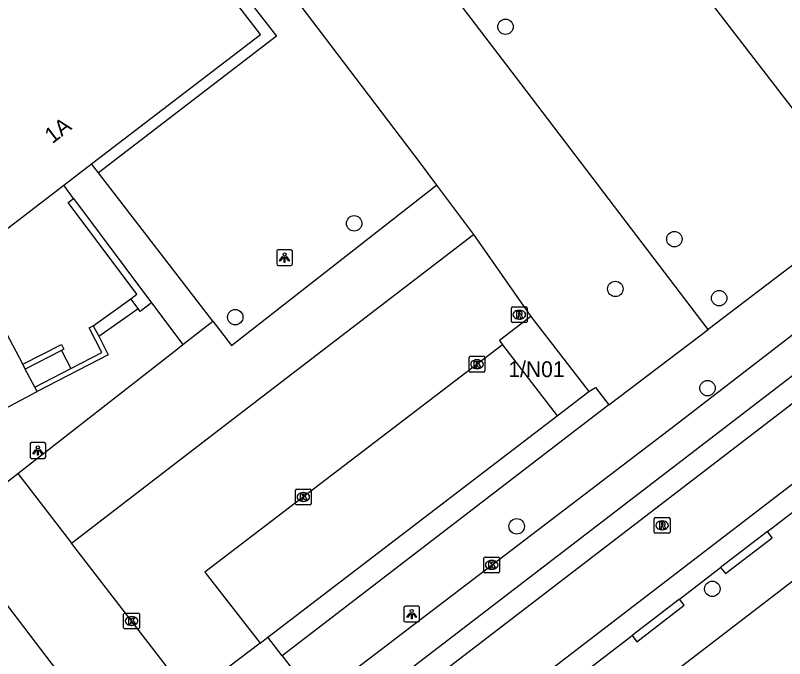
# Model space of a CAD drawing. Extents: x 159353 to 160616, y 385893 to 387321.
# Drawn here: x 159907.94 to 159956.75, y 386515.87 to 386556.66 of the extents above; entities that cross this region are included whole.
import ezdxf

# ---------------------------------------------------------------- set-up
doc = ezdxf.new("R2010")
doc.units = 0
for name, color, linetype in [('IMGEO_Boom', 7, 'Continuous'), ('IMGEO_Groenvoorziening', 7, 'Continuous'), ('IMGEO_Haag', 7, 'Continuous'), ('IMGEO_Kolk', 7, 'Continuous'), ('IMGEO_Lichtpunt', 7, 'Continuous'), ('IMGEO_Muur', 7, 'Continuous'), ('IMGEO_Pand', 7, 'Continuous'), ('IMGEO_Pand_nummerreeks', 7, 'Continuous'), ('IMGEO_Parkeervlak_open', 7, 'Continuous'), ('IMGEO_Rijbaan_lokaal_gesloten', 7, 'Continuous'), ('IMGEO_Rijbaan_lokaal_open', 7, 'Continuous'), ('IMGEO_Rioolput', 7, 'Continuous'), ('IMGEO_Voetpad_open', 7, 'Continuous')]:
    doc.layers.add(name, color=color, linetype=linetype)

msp = doc.modelspace()

# ---------------------------------------------------------------- linework, layer by layer
at = {"layer": 'IMGEO_Boom'}
for centre in [(159939.044, 386555.938), (159929.438, 386543.471), (159949.759, 386542.469), (159946.013, 386539.313), (159952.603, 386538.727), (159921.896, 386537.523), (159951.858, 386533.017), (159939.754, 386524.256), (159952.169, 386520.29)]:
    msp.add_circle(centre, 0.489, dxfattribs=at)
at = {"layer": 'IMGEO_Groenvoorziening'}
for points in [[(159951.895, 386536.745), (159940.008, 386552.331), (159922.277, 386575.578), (159898.089, 386607.292)], [(159918.33, 386563.284), (159920.36, 386564.743), (159933.568, 386547.368), (159934.672, 386545.892)], [(159918.33, 386563.284), (159924.505, 386555.352), (159913.211, 386546.671)]]:
    msp.add_lwpolyline(points, dxfattribs=at)
at = {"layer": 'IMGEO_Haag'}
msp.add_lwpolyline([(159944.324, 386532.797), (159944.745, 386533.066), (159945.59, 386531.953)], dxfattribs=at)
at = {"layer": 'IMGEO_Kolk'}
for p, q in [((159936.738, 386534.112), (159936.738, 386534.964)), ((159936.813, 386535.038), (159937.665, 386535.038)), ((159937.226, 386534.818), (159937.251, 386534.818)), ((159937.739, 386534.964), (159937.739, 386534.112)), ((159937.249, 386534.258), (159937.224, 386534.258)), ((159937.665, 386534.038), (159936.813, 386534.038)), ((159925.714, 386525.691), (159925.714, 386526.543)), ((159925.789, 386526.617), (159926.641, 386526.617)), ((159926.202, 386526.397), (159926.227, 386526.397)), ((159926.715, 386526.543), (159926.715, 386525.691)), ((159926.225, 386525.837), (159926.2, 386525.837)), ((159926.641, 386525.617), (159925.789, 386525.617)), ((159937.669, 386521.384), (159937.669, 386522.236)), ((159937.744, 386522.31), (159938.596, 386522.31)), ((159938.157, 386522.09), (159938.182, 386522.09)), ((159938.67, 386522.236), (159938.67, 386521.384)), ((159938.18, 386521.53), (159938.155, 386521.53)), ((159938.596, 386521.31), (159937.744, 386521.31)), ((159914.814, 386517.826), (159914.814, 386518.678)), ((159914.889, 386518.752), (159915.741, 386518.752)), ((159915.302, 386518.532), (159915.327, 386518.532)), ((159915.815, 386518.678), (159915.815, 386517.826)), ((159915.741, 386517.752), (159914.889, 386517.752)), ((159915.325, 386517.972), (159915.3, 386517.972))]:
    msp.add_line(p, q, dxfattribs=at)
for points in [[(159936.738, 386534.112), (159936.738, 386534.964)], [(159936.813, 386535.038), (159937.665, 386535.038)], [(159937.059, 386534.738), (159937.182, 386534.738), (159937.182, 386534.587), (159937.312, 386534.738), (159937.476, 386534.738), (159937.33, 386534.587), (159937.483, 386534.338), (159937.331, 386534.338), (159937.246, 386534.502), (159937.182, 386534.435), (159937.182, 386534.338), (159937.059, 386534.338), (159937.059, 386534.738)], [(159937.739, 386534.964), (159937.739, 386534.112)], [(159937.665, 386534.038), (159936.813, 386534.038)], [(159925.714, 386525.691), (159925.714, 386526.543)], [(159925.789, 386526.617), (159926.641, 386526.617)], [(159926.715, 386526.543), (159926.715, 386525.691)], [(159926.035, 386526.317), (159926.158, 386526.317), (159926.158, 386526.166), (159926.288, 386526.317), (159926.452, 386526.317), (159926.306, 386526.166), (159926.459, 386525.917), (159926.307, 386525.917), (159926.222, 386526.081), (159926.158, 386526.014), (159926.158, 386525.917), (159926.035, 386525.917), (159926.035, 386526.317)], [(159926.641, 386525.617), (159925.789, 386525.617)], [(159937.669, 386521.384), (159937.669, 386522.236)], [(159937.744, 386522.31), (159938.596, 386522.31)], [(159937.99, 386522.01), (159938.113, 386522.01), (159938.113, 386521.859), (159938.243, 386522.01), (159938.407, 386522.01), (159938.261, 386521.859), (159938.414, 386521.61), (159938.262, 386521.61), (159938.177, 386521.774), (159938.113, 386521.707), (159938.113, 386521.61), (159937.99, 386521.61), (159937.99, 386522.01)], [(159938.67, 386522.236), (159938.67, 386521.384)], [(159938.596, 386521.31), (159937.744, 386521.31)], [(159914.814, 386517.826), (159914.814, 386518.678)], [(159914.889, 386518.752), (159915.741, 386518.752)], [(159915.815, 386518.678), (159915.815, 386517.826)], [(159915.135, 386518.452), (159915.258, 386518.452), (159915.258, 386518.301), (159915.388, 386518.452), (159915.552, 386518.452), (159915.406, 386518.301), (159915.559, 386518.052), (159915.407, 386518.052), (159915.322, 386518.216), (159915.258, 386518.149), (159915.258, 386518.052), (159915.135, 386518.052), (159915.135, 386518.452)], [(159915.741, 386517.752), (159914.889, 386517.752)]]:
    msp.add_lwpolyline(points, dxfattribs=at)
for centre, start, end in [((159936.815, 386534.962), 91.552, 178.448), ((159936.815, 386534.962), 91.552, 178.448), ((159937.663, 386534.962), 1.552, 88.448), ((159937.663, 386534.962), 1.552, 88.448), ((159936.815, 386534.114), 181.552, 268.448), ((159936.815, 386534.114), 181.552, 268.448), ((159937.663, 386534.114), 271.552, 358.448), ((159937.663, 386534.114), 271.552, 358.448), ((159925.791, 386526.541), 91.552, 178.448), ((159925.791, 386526.541), 91.552, 178.448), ((159926.639, 386526.541), 1.552, 88.448), ((159926.639, 386526.541), 1.552, 88.448), ((159925.791, 386525.693), 181.552, 268.448), ((159925.791, 386525.693), 181.552, 268.448), ((159926.639, 386525.693), 271.552, 358.448), ((159926.639, 386525.693), 271.552, 358.448), ((159937.746, 386522.234), 91.552, 178.448), ((159937.746, 386522.234), 91.552, 178.448), ((159938.594, 386522.234), 1.552, 88.448), ((159938.594, 386522.234), 1.552, 88.448), ((159937.746, 386521.386), 181.552, 268.448), ((159937.746, 386521.386), 181.552, 268.448), ((159938.594, 386521.386), 271.552, 358.448), ((159938.594, 386521.386), 271.552, 358.448), ((159914.891, 386518.676), 91.552, 178.448), ((159914.891, 386518.676), 91.552, 178.448), ((159915.739, 386518.676), 1.552, 88.448), ((159915.739, 386518.676), 1.552, 88.448), ((159914.891, 386517.828), 181.552, 268.448), ((159914.891, 386517.828), 181.552, 268.448), ((159915.739, 386517.828), 271.552, 358.448), ((159915.739, 386517.828), 271.552, 358.448)]:
    msp.add_arc(centre, 0.0765, start, end, dxfattribs=at)
for centre, major_axis, ratio, start_param, end_param in [((159937.225, 386534.538), (-0.387, 0.002), 0.722429, 4.712389, 7.853982), ((159937.25, 386534.538), (-0.39, 0.002), 0.717154, 1.570796, 4.712389), ((159926.201, 386526.117), (-0.387, 0.002), 0.722429, 4.712389, 7.853982), ((159926.226, 386526.117), (-0.39, 0.002), 0.717154, 1.570796, 4.712389), ((159938.156, 386521.81), (-0.387, 0.002), 0.722429, 4.712389, 7.853982), ((159938.181, 386521.81), (-0.39, 0.002), 0.717154, 1.570796, 4.712389), ((159915.301, 386518.252), (-0.387, 0.002), 0.722429, 4.712389, 7.853982), ((159915.326, 386518.252), (-0.39, 0.002), 0.717154, 1.570796, 4.712389)]:
    msp.add_ellipse(centre, major_axis=major_axis, ratio=ratio, start_param=start_param, end_param=end_param, dxfattribs=at)
at = {"layer": 'IMGEO_Lichtpunt'}
for p, q in [((159924.526, 386541.701), (159924.526, 386540.894)), ((159924.526, 386541.701), (159924.526, 386540.894)), ((159925.428, 386541.796), (159924.62, 386541.796)), ((159925.428, 386541.796), (159924.62, 386541.796)), ((159925.522, 386540.894), (159925.522, 386541.701)), ((159925.522, 386540.894), (159925.522, 386541.701)), ((159924.62, 386540.8), (159925.428, 386540.8)), ((159924.62, 386540.8), (159925.428, 386540.8)), ((159908.872, 386529.468), (159908.872, 386528.661)), ((159908.872, 386529.468), (159908.872, 386528.661)), ((159909.774, 386529.563), (159908.966, 386529.563)), ((159909.774, 386529.563), (159908.966, 386529.563)), ((159909.868, 386528.661), (159909.868, 386529.468)), ((159909.868, 386528.661), (159909.868, 386529.468)), ((159908.966, 386528.567), (159909.774, 386528.567)), ((159908.966, 386528.567), (159909.774, 386528.567)), ((159932.594, 386519.092), (159932.594, 386518.285)), ((159932.594, 386519.092), (159932.594, 386518.285)), ((159933.496, 386519.187), (159932.688, 386519.187)), ((159933.496, 386519.187), (159932.688, 386519.187)), ((159933.59, 386518.285), (159933.59, 386519.092)), ((159933.59, 386518.285), (159933.59, 386519.092)), ((159932.688, 386518.191), (159933.496, 386518.191)), ((159932.688, 386518.191), (159933.496, 386518.191))]:
    msp.add_line(p, q, dxfattribs=at)
for points in [[(159924.9, 386541.365), (159924.939, 386541.337), (159924.751, 386541.075), (159924.713, 386541.102), (159924.9, 386541.365)], [(159925.002, 386541.317), (159925.049, 386541.317), (159925.049, 386540.995), (159925.002, 386540.995), (159925.002, 386541.317)], [(159925.112, 386541.337), (159925.15, 386541.364), (159925.337, 386541.102), (159925.298, 386541.074), (159925.112, 386541.337)], [(159909.246, 386529.132), (159909.285, 386529.104), (159909.097, 386528.842), (159909.059, 386528.869), (159909.246, 386529.132)], [(159909.348, 386529.084), (159909.395, 386529.084), (159909.395, 386528.762), (159909.348, 386528.762), (159909.348, 386529.084)], [(159909.458, 386529.104), (159909.496, 386529.131), (159909.683, 386528.869), (159909.644, 386528.841), (159909.458, 386529.104)], [(159932.968, 386518.756), (159933.007, 386518.728), (159932.819, 386518.466), (159932.781, 386518.493), (159932.968, 386518.756)], [(159933.07, 386518.708), (159933.117, 386518.708), (159933.117, 386518.386), (159933.07, 386518.386), (159933.07, 386518.708)], [(159933.18, 386518.728), (159933.218, 386518.755), (159933.405, 386518.493), (159933.366, 386518.465), (159933.18, 386518.728)]]:
    msp.add_lwpolyline(points, dxfattribs=at)
for centre in [(159925.025, 386541.499), (159909.371, 386529.266), (159933.093, 386518.89)]:
    msp.add_circle(centre, 0.0994, dxfattribs=at)
for centre, start, end in [((159924.62, 386541.701), 90, 180), ((159924.62, 386541.701), 90, 180), ((159925.428, 386541.701), 0, 90), ((159925.428, 386541.701), 0, 90), ((159924.62, 386540.894), 180, 270), ((159924.62, 386540.894), 180, 270), ((159925.428, 386540.894), 270, 0), ((159925.428, 386540.894), 270, 360), ((159908.966, 386529.468), 90, 180), ((159908.966, 386529.468), 90, 180), ((159909.774, 386529.468), 0, 90), ((159909.774, 386529.468), 0, 90), ((159908.966, 386528.661), 180, 270), ((159908.966, 386528.661), 180, 270), ((159909.774, 386528.661), 270, 0), ((159909.774, 386528.661), 270, 360), ((159932.688, 386519.092), 90, 180), ((159932.688, 386519.092), 90, 180), ((159933.496, 386519.092), 0, 90), ((159933.496, 386519.092), 0, 90), ((159932.688, 386518.285), 180, 270), ((159932.688, 386518.285), 180, 270), ((159933.496, 386518.285), 270, 0), ((159933.496, 386518.285), 270, 360)]:
    msp.add_arc(centre, 0.0946, start, end, dxfattribs=at)
at = {"layer": 'IMGEO_Muur'}
for points in [[(159915.277, 386538.684), (159915.64, 386538.98), (159911.292, 386544.804), (159911.633, 386545.058)], [(159911.633, 386545.058), (159916.586, 386538.424)], [(159915.736, 386538.069), (159915.277, 386538.684)], [(159916.586, 386538.424), (159915.87, 386537.889), (159915.736, 386538.069)], [(159911.459, 386534.256), (159913.433, 386535.272), (159912.622, 386536.846), (159912.886, 386536.982)], [(159912.886, 386536.982), (159913.229, 386536.316)], [(159913.229, 386536.316), (159913.837, 386535.135), (159909.321, 386532.811)], [(159908.409, 386534.534), (159910.864, 386535.798), (159911.024, 386535.487), (159910.866, 386535.406)], [(159910.866, 386535.406), (159908.573, 386534.224)], [(159909.178, 386533.081), (159911.459, 386534.256)]]:
    msp.add_lwpolyline(points, dxfattribs=at)
at = {"layer": 'IMGEO_Pand'}
for points in [[(159955.838, 386571.648), (159967.738, 386556.2), (159958.533, 386549.121), (159946.634, 386564.57)], [(159912.775, 386547.236), (159923.497, 386555.45), (159920.456, 386559.419), (159917.807, 386562.877)], [(159911.014, 386545.887), (159912.775, 386547.236)], [(159908.409, 386534.534), (159904.884, 386541.191), (159911.014, 386545.887)], [(159940.649, 386537.568), (159938.657, 386536.034), (159938.858, 386535.773)], [(159940.649, 386537.568), (159944.324, 386532.797)], [(159938.858, 386535.773), (159942.332, 386531.263)], [(159897.179, 386534.822), (159901.779, 386528.816), (159909.321, 386532.811)], [(159908.573, 386534.224), (159908.409, 386534.534)], [(159909.178, 386533.081), (159908.573, 386534.224)], [(159909.321, 386532.811), (159909.178, 386533.081)], [(159942.332, 386531.263), (159944.324, 386532.797)]]:
    msp.add_lwpolyline(points, dxfattribs=at)
at = {"layer": 'IMGEO_Parkeervlak_open'}
for points in [[(159920.47, 386537.273), (159921.661, 386535.731), (159934.672, 386545.892)], [(159934.672, 386545.892), (159937.004, 386542.774)], [(159923.967, 386517.223), (159942.332, 386531.263)], [(159908.093, 386527.599), (159911.495, 386523.195)], [(159914.482, 386510.005), (159906.02, 386521.077), (159905.493, 386521.701)]]:
    msp.add_lwpolyline(points, dxfattribs=at)
at = {"layer": 'IMGEO_Rijbaan_lokaal_gesloten'}
for points in [[(159876.924, 386472.328), (159899.739, 386489.718), (159978.286, 386549.954)], [(159859.708, 386457.258), (159979.14, 386548.844)], [(159981.625, 386545.617), (159862.162, 386454.007)], [(159955.666, 386523.932), (159962.814, 386529.415)], [(159955.666, 386523.932), (159952.696, 386521.654)], [(159950.078, 386519.645), (159952.696, 386521.654)], [(159950.078, 386519.645), (159947.079, 386517.33)], [(159938.561, 386510.815), (159944.357, 386515.23), (159947.079, 386517.33)]]:
    msp.add_lwpolyline(points, dxfattribs=at)
at = {"layer": 'IMGEO_Rijbaan_lokaal_open'}
for points in [[(159911.495, 386523.195), (159921.481, 386530.86), (159937.004, 386542.774)], [(159937.004, 386542.774), (159940.649, 386537.568)], [(159938.858, 386535.773), (159919.966, 386521.341), (159923.468, 386516.842)], [(159919.018, 386513.456), (159911.495, 386523.195)], [(159923.468, 386516.842), (159919.018, 386513.456)]]:
    msp.add_lwpolyline(points, dxfattribs=at)
at = {"layer": 'IMGEO_Rioolput'}
for p, q in [((159939.414, 386537.249), (159939.414, 386538.101)), ((159939.489, 386538.175), (159940.341, 386538.175)), ((159940.415, 386538.101), (159940.415, 386537.249)), ((159939.902, 386537.955), (159939.927, 386537.955)), ((159940.341, 386537.175), (159939.489, 386537.175)), ((159939.925, 386537.395), (159939.9, 386537.395)), ((159948.481, 386523.89), (159948.481, 386524.742)), ((159948.556, 386524.816), (159949.408, 386524.816)), ((159948.969, 386524.596), (159948.994, 386524.596)), ((159949.482, 386524.742), (159949.482, 386523.89)), ((159948.992, 386524.036), (159948.967, 386524.036)), ((159949.408, 386523.816), (159948.556, 386523.816))]:
    msp.add_line(p, q, dxfattribs=at)
for points in [[(159939.414, 386537.249), (159939.414, 386538.101)], [(159939.489, 386538.175), (159940.341, 386538.175)], [(159940.415, 386538.101), (159940.415, 386537.249)], [(159940.003, 386537.873), (159939.751, 386537.875), (159939.751, 386537.475)], [(159939.751, 386537.475), (159939.875, 386537.475), (159939.875, 386537.637), (159939.886, 386537.637)], [(159939.929, 386537.794), (159939.875, 386537.794), (159939.875, 386537.713)], [(159939.875, 386537.713), (159939.927, 386537.713)], [(159939.933, 386537.608), (159940.004, 386537.475), (159940.144, 386537.475), (159940.079, 386537.601)], [(159940.341, 386537.175), (159939.489, 386537.175)], [(159948.481, 386523.89), (159948.481, 386524.742)], [(159948.556, 386524.816), (159949.408, 386524.816)], [(159949.07, 386524.514), (159948.818, 386524.516), (159948.818, 386524.116)], [(159948.996, 386524.435), (159948.942, 386524.435), (159948.942, 386524.354)], [(159949.482, 386524.742), (159949.482, 386523.89)], [(159948.818, 386524.116), (159948.942, 386524.116), (159948.942, 386524.278), (159948.953, 386524.278)], [(159948.942, 386524.354), (159948.994, 386524.354)], [(159949, 386524.249), (159949.071, 386524.116), (159949.211, 386524.116), (159949.146, 386524.242)], [(159949.408, 386523.816), (159948.556, 386523.816)]]:
    msp.add_lwpolyline(points, dxfattribs=at)
for centre, radius, start, end in [((159939.491, 386538.099), 0.0765, 91.552, 178.448), ((159939.491, 386538.099), 0.0765, 91.552, 178.448), ((159940.339, 386538.099), 0.0765, 1.552, 88.448), ((159940.339, 386538.099), 0.0765, 1.552, 88.448), ((159939.885, 386537.584), 0.0533, 26.0293, 88.6989), ((159939.911, 386537.902), 0.19, 274.7715, 282.9687), ((159939.935, 386537.698), 0.0964, 77.0061, 93.1865), ((159939.949, 386537.755), 0.0378, 276.6634, 79.6772), ((159940.002, 386537.763), 0.109, 350.3612, 89.416), ((159940, 386537.763), 0.112, 277.5842, 350.9817), ((159939.984, 386537.548), 0.108, 29.5134, 73.7905), ((159939.491, 386537.251), 0.0765, 181.552, 268.448), ((159939.491, 386537.251), 0.0765, 181.552, 268.448), ((159940.339, 386537.251), 0.0765, 271.552, 358.448), ((159940.339, 386537.251), 0.0765, 271.552, 358.448), ((159948.558, 386524.74), 0.0765, 91.552, 178.448), ((159948.558, 386524.74), 0.0765, 91.552, 178.448), ((159949.002, 386524.339), 0.0964, 77.0061, 93.1865), ((159949.016, 386524.396), 0.0378, 276.6634, 79.6772), ((159949.069, 386524.404), 0.109, 350.3612, 89.416), ((159949.067, 386524.404), 0.112, 277.5842, 350.9817), ((159949.406, 386524.74), 0.0765, 1.552, 88.448), ((159949.406, 386524.74), 0.0765, 1.552, 88.448), ((159948.558, 386523.892), 0.0765, 181.552, 268.448), ((159948.558, 386523.892), 0.0765, 181.552, 268.448), ((159948.952, 386524.225), 0.0533, 26.0293, 88.6989), ((159948.978, 386524.543), 0.19, 274.7715, 282.9687), ((159949.051, 386524.189), 0.108, 29.5134, 73.7905), ((159949.406, 386523.892), 0.0765, 271.552, 358.448), ((159949.406, 386523.892), 0.0765, 271.552, 358.448)]:
    msp.add_arc(centre, radius, start, end, dxfattribs=at)
for centre, major_axis, ratio, start_param, end_param in [((159939.901, 386537.675), (-0.387, 0.002), 0.722429, 4.712389, 7.853982), ((159939.926, 386537.675), (-0.39, 0.002), 0.717154, 1.570796, 4.712389), ((159948.968, 386524.316), (-0.387, 0.002), 0.722429, 4.712389, 7.853982), ((159948.993, 386524.316), (-0.39, 0.002), 0.717154, 1.570796, 4.712389)]:
    msp.add_ellipse(centre, major_axis=major_axis, ratio=ratio, start_param=start_param, end_param=end_param, dxfattribs=at)
at = {"layer": 'IMGEO_Voetpad_open'}
for points in [[(159972.553, 386552.445), (159951.895, 386536.745)], [(159926.982, 386513.283), (159949.802, 386530.673), (159970.339, 386546.5), (159974.688, 386549.863)], [(159913.211, 386546.671), (159912.775, 386547.236)], [(159920.47, 386537.273), (159913.211, 386546.671)], [(159911.633, 386545.058), (159911.014, 386545.887)], [(159984.546, 386541.708), (159952.365, 386517.008), (159930.173, 386500), (159908.837, 386483.648)], [(159912.886, 386536.982), (159915.277, 386538.684)], [(159913.229, 386536.316), (159915.736, 386538.069)], [(159916.586, 386538.424), (159918.56, 386535.78)], [(159918.56, 386535.78), (159920.47, 386537.273)], [(159945.59, 386531.953), (159951.895, 386536.745)], [(159908.093, 386527.599), (159918.014, 386535.354), (159918.56, 386535.78)], [(159910.866, 386535.406), (159911.459, 386534.256)], [(159945.59, 386531.953), (159924.868, 386516.046)], [(159903.673, 386524.147), (159908.093, 386527.599)], [(159952.696, 386521.654), (159953, 386521.258), (159955.97, 386523.536), (159955.666, 386523.932)], [(159947.079, 386517.33), (159947.383, 386516.936), (159950.383, 386519.25), (159950.078, 386519.645)], [(159923.468, 386516.842), (159923.967, 386517.223)], [(159924.868, 386516.046), (159923.967, 386517.223)], [(159924.868, 386516.046), (159926.982, 386513.283)]]:
    msp.add_lwpolyline(points, dxfattribs=at)

# ---------------------------------------------------------------- texts
at = {"layer": 'IMGEO_Pand_nummerreeks'}
msp.add_text('1A', height=1, rotation=37.4549, dxfattribs=at).set_placement((159910.289, 386548.487))
msp.add_text('1/N01', height=1, dxfattribs=at).set_placement((159939.222, 386533.721))

doc.saveas('drawing.dxf')
